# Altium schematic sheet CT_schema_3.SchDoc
size 276 x 169 mm
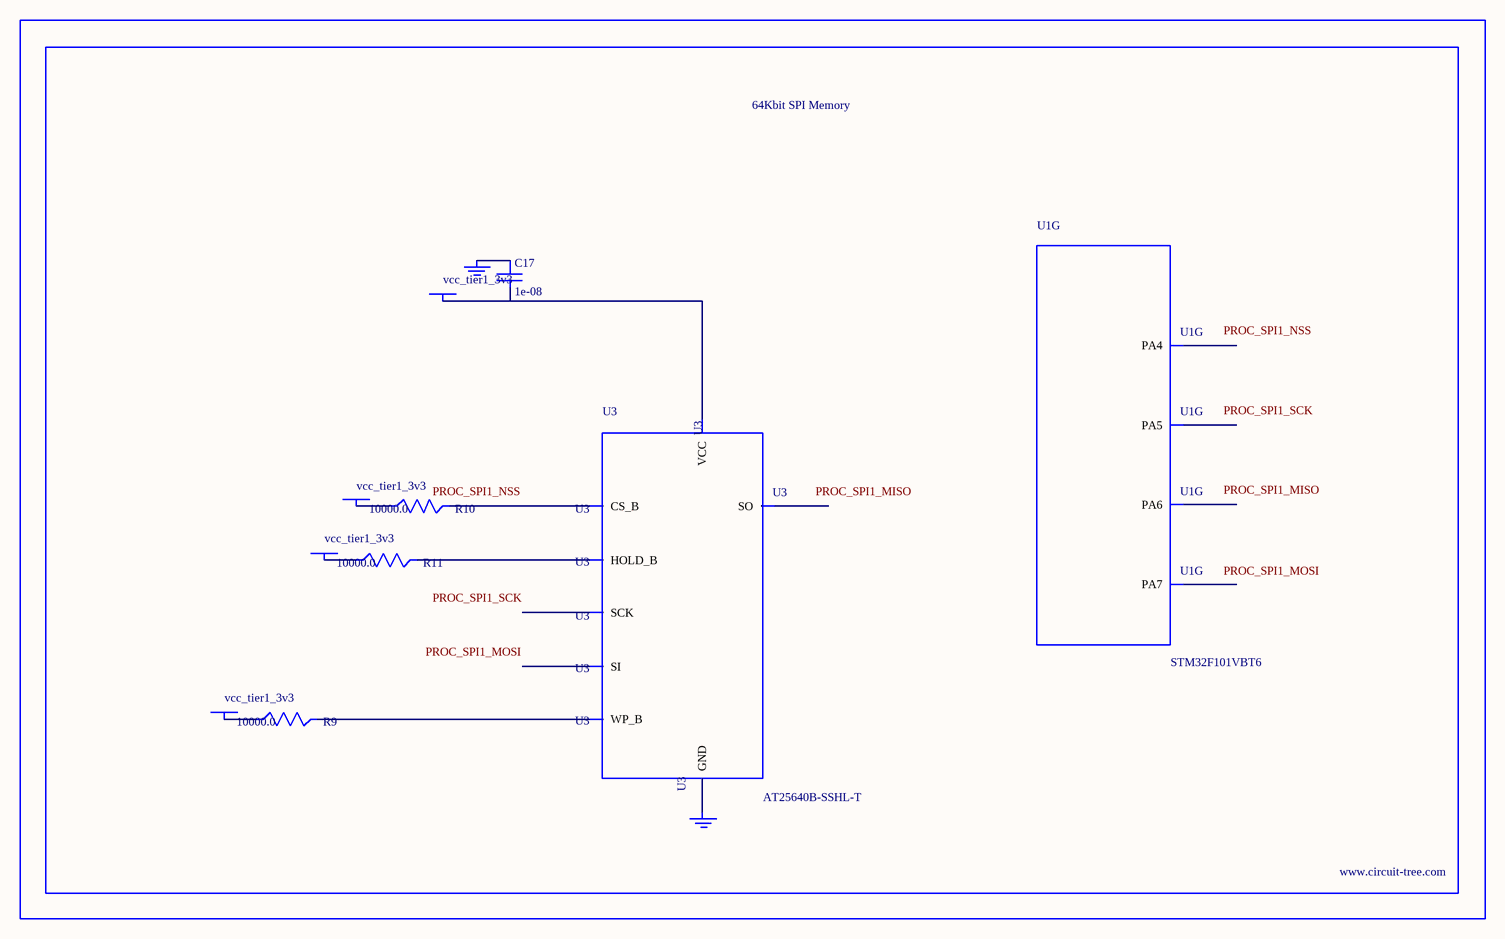
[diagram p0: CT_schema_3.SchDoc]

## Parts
BORDER2  (no value)
C17  1e-08  [C0402]
GND_INSTANCE_2_0  (no value)
GND_INSTANCE_2_1  (no value)
POWER_INSTANCE_2_0  vcc_tier1_3v3
POWER_INSTANCE_2_1  vcc_tier1_3v3
POWER_INSTANCE_2_2  vcc_tier1_3v3
POWER_INSTANCE_2_3  vcc_tier1_3v3
R9  10000.0  [R0603]
R10  10000.0  [R0603]
R11  10000.0  [R0603]
U1  STM32F101VBT6  [LQFP100]  (part G of 9)
U3  AT25640B-SSHL-T  [SOIC-8]

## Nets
NetC17_1: C17.1 GND_INSTANCE_2_0.0(GND)
NetC17_2: C17.2 POWER_INSTANCE_2_3.0(PWR) U3.8(VCC)
NetGND_INSTANCE_2_1_0: GND_INSTANCE_2_1.0(GND) U3.4(GND)
NetPOWER_INSTANCE_2_0_0: POWER_INSTANCE_2_0.0(PWR) R10.1
NetPOWER_INSTANCE_2_1_0: POWER_INSTANCE_2_1.0(PWR) R9.1
NetPOWER_INSTANCE_2_2_0: POWER_INSTANCE_2_2.0(PWR) R11.1
NetR9_2: R9.2 U3.3(WP_B)
NetR10_2: R10.2 U3.1(CS_B)
NetR11_2: R11.2 U3.7(HOLD_B)

Not connected (* = marked no-connect by the designer): U1 29(PA4) 30(PA5) 31(PA6) 32(PA7); U3 2(SO) 5(SI) 6(SCK)

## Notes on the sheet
- Labels drawn without touching a wire or pin: PROC_SPI1_MISO, PROC_SPI1_MOSI, PROC_SPI1_NSS, PROC_SPI1_SCK

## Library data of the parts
BORDER2 = BORDER_PAGE2
C17 = C0402C103K3RAC
GND_INSTANCE_2_0 GND_INSTANCE_2_1 = GND
POWER_INSTANCE_2_0-POWER_INSTANCE_2_3 = PWR
R9-R11 = RC0603JR-0710KL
